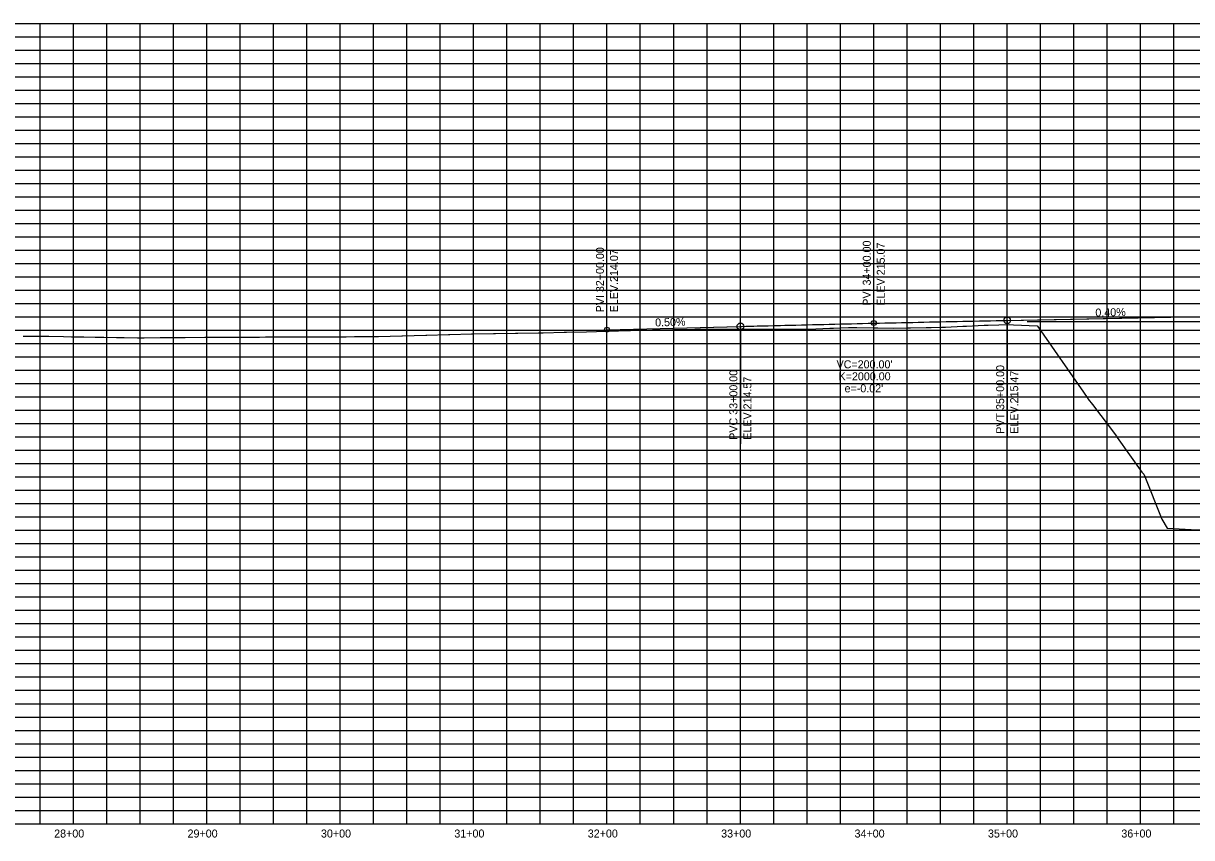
# Model space of a CAD drawing. Extents: x 1732967 to 1742744, y 374025 to 374739.
# Drawn here: x 1740676 to 1741552, y 374119 to 374730 of the extents above; entities that cross this region are included whole.
import ezdxf

# ---------------------------------------------------------------- set-up
doc = ezdxf.new("R2010")
doc.units = 0
for name, color, linetype in [('Level 8', 7, 'Continuous'), ('R_Axis_Annotation', 7, 'Continuous'), ('R_Exist Surface', 7, 'Continuous'), ('R_Grid', 7, 'Continuous'), ('R_Grid_Minor', 7, 'Continuous'), ('R_Horz Alg', 7, 'Continuous'), ('R_Vert Alg', 7, 'Continuous'), ('R_Vert Alg Annot', 7, 'Continuous')]:
    doc.layers.add(name, color=color, linetype=linetype)

msp = doc.modelspace()

# ---------------------------------------------------------------- linework, layer by layer
at = {"layer": 'Level 8'}
msp.add_line((1741428.91, 374506.11), (1741983.91, 374506.11), dxfattribs=at)
at = {"layer": 'R_Exist Surface'}
msp.add_lwpolyline([(1740676.24, 374495.2), (1740677.05, 374495.2), (1740677.87, 374495.19), (1740691.37, 374495.12), (1740694.78, 374495.1), (1740695.45, 374495.09), (1740706.51, 374494.86), (1740712.48, 374494.73), (1740712.84, 374494.72), (1740721.65, 374494.53), (1740730.12, 374494.34), (1740730.22, 374494.34), (1740734.41, 374494.29), (1740736.79, 374494.26), (1740746.31, 374494.14), (1740751.93, 374494.07), (1740761.89, 374493.94), (1740762.41, 374493.93), (1740767.07, 374493.97), (1740778.92, 374494.06), (1740779.59, 374494.07), (1740780.26, 374494.08), (1740782.21, 374494.1), (1740796.76, 374494.22), (1740797.35, 374494.23), (1740797.6, 374494.23), (1740812.49, 374494.26), (1740815.52, 374494.27), (1740827.62, 374494.29), (1740833.23, 374494.3), (1740834.28, 374494.32), (1740842.76, 374494.4), (1740851.74, 374494.48), (1740852.56, 374494.48), (1740853.37, 374494.48), (1740857.9, 374494.52), (1740870.85, 374494.64), (1740871.42, 374494.63), (1740873.04, 374494.63), (1740888.18, 374494.62), (1740888.8, 374494.62), (1740889.33, 374494.62), (1740903.32, 374494.6), (1740906.74, 374494.6), (1740907.14, 374494.6), (1740918.46, 374494.72), (1740924.63, 374494.79), (1740924.78, 374494.79), (1740933.6, 374494.88), (1740934.17, 374494.89), (1740942.36, 374494.96), (1740942.51, 374494.96), (1740960.24, 374495.4), (1740960.63, 374495.42), (1740978.12, 374495.86), (1740978.74, 374495.87), (1740995.2, 374496.35), (1740996.11, 374496.37), (1741012.27, 374496.84), (1741013.48, 374496.87), (1741028.86, 374497.05), (1741030.23, 374497.07), (1741045.39, 374497.25), (1741046.98, 374497.28), (1741062.63, 374497.62), (1741064.36, 374497.65), (1741066.1, 374497.68), (1741081.73, 374498.03), (1741083.51, 374498.08), (1741098.5, 374498.43), (1741113.53, 374498.78), (1741115.28, 374498.83), (1741130.01, 374499.24), (1741131.65, 374499.3), (1741146.46, 374499.71), (1741148.02, 374499.76), (1741163.15, 374500.03), (1741164.53, 374500.01), (1741179.86, 374500.29), (1741181.05, 374500.28), (1741182.06, 374500.3), (1741193.99, 374500.4), (1741195.28, 374500.44), (1741209.02, 374500.42), (1741221.06, 374500.42), (1741222.66, 374500.43), (1741234.83, 374500.44), (1741236.17, 374500.48), (1741247.91, 374500.42), (1741248.97, 374500.45), (1741260.84, 374500.39), (1741264.71, 374500.44), (1741265.34, 374500.46), (1741270.46, 374500.73), (1741280.85, 374501.18), (1741283.71, 374501.16), (1741294.89, 374501.66), (1741297.53, 374501.62), (1741301.32, 374501.54), (1741313.37, 374501.35), (1741316.86, 374501.37), (1741328.59, 374501.19), (1741338.49, 374501.27), (1741341.56, 374501.4), (1741353.1, 374501.61), (1741355.53, 374501.68), (1741356.85, 374501.73), (1741364.75, 374501.85), (1741367.72, 374501.96), (1741380.71, 374502.55), (1741383.49, 374502.65), (1741396.66, 374503.25), (1741399.56, 374503.37), (1741415.69, 374503.77), (1741418.61, 374503.53), (1741436.4, 374502.88), (1741437.34, 374501.71), (1741471.07, 374453.23), (1741474.45, 374448.32), (1741474.59, 374448.19), (1741474.74, 374448), (1741477.82, 374443.92), (1741495.83, 374420.05), (1741496.41, 374419.24), (1741514.96, 374393.26), (1741516.32, 374391.71), (1741516.41, 374391.65), (1741517.15, 374389.91), (1741529.42, 374359.27), (1741529.95, 374357.89), (1741533.72, 374351.3), (1741551.93, 374350.3), (1741558.51, 374349.94)], dxfattribs=at)
at = {"layer": 'R_Grid'}
for p, q in [((1739913.91, 374729.61), (1742713.91, 374729.61)), ((1740713.91, 374129.61), (1740713.91, 374729.61)), ((1740813.91, 374129.61), (1740813.91, 374729.61)), ((1740913.91, 374129.61), (1740913.91, 374729.61)), ((1741013.91, 374129.61), (1741013.91, 374729.61)), ((1741113.91, 374129.61), (1741113.91, 374729.61)), ((1741213.91, 374129.61), (1741213.91, 374729.61)), ((1741313.91, 374129.61), (1741313.91, 374729.61)), ((1741413.91, 374129.61), (1741413.91, 374729.61)), ((1741513.91, 374129.61), (1741513.91, 374729.61)), ((1739913.91, 374679.61), (1742713.91, 374679.61)), ((1739913.91, 374629.61), (1742713.91, 374629.61)), ((1739913.91, 374579.61), (1742713.91, 374579.61)), ((1739913.91, 374529.61), (1742713.91, 374529.61)), ((1739913.91, 374479.61), (1742713.91, 374479.61)), ((1739913.91, 374429.61), (1742713.91, 374429.61)), ((1739913.91, 374379.61), (1742713.91, 374379.61)), ((1739913.91, 374329.61), (1742713.91, 374329.61)), ((1739913.91, 374279.61), (1742713.91, 374279.61)), ((1739913.91, 374229.61), (1742713.91, 374229.61)), ((1739913.91, 374179.61), (1742713.91, 374179.61)), ((1739913.91, 374129.61), (1742713.91, 374129.61))]:
    msp.add_line(p, q, dxfattribs=at)
at = {"layer": 'R_Grid_Minor'}
for p, q in [((1740688.91, 374129.61), (1740688.91, 374729.61)), ((1740738.91, 374129.61), (1740738.91, 374729.61)), ((1740763.91, 374129.61), (1740763.91, 374729.61)), ((1740788.91, 374129.61), (1740788.91, 374729.61)), ((1740838.91, 374129.61), (1740838.91, 374729.61)), ((1740863.91, 374129.61), (1740863.91, 374729.61)), ((1740888.91, 374129.61), (1740888.91, 374729.61)), ((1740938.91, 374129.61), (1740938.91, 374729.61)), ((1740963.91, 374129.61), (1740963.91, 374729.61)), ((1740988.91, 374129.61), (1740988.91, 374729.61)), ((1741038.91, 374129.61), (1741038.91, 374729.61)), ((1741063.91, 374129.61), (1741063.91, 374729.61)), ((1741088.91, 374129.61), (1741088.91, 374729.61)), ((1741138.91, 374129.61), (1741138.91, 374729.61)), ((1741163.91, 374129.61), (1741163.91, 374729.61)), ((1741188.91, 374129.61), (1741188.91, 374729.61)), ((1741238.91, 374129.61), (1741238.91, 374729.61)), ((1741263.91, 374129.61), (1741263.91, 374729.61)), ((1741288.91, 374129.61), (1741288.91, 374729.61)), ((1741338.91, 374129.61), (1741338.91, 374729.61)), ((1741363.91, 374129.61), (1741363.91, 374729.61)), ((1741388.91, 374129.61), (1741388.91, 374729.61)), ((1741438.91, 374129.61), (1741438.91, 374729.61)), ((1741463.91, 374129.61), (1741463.91, 374729.61)), ((1741488.91, 374129.61), (1741488.91, 374729.61)), ((1741538.91, 374129.61), (1741538.91, 374729.61)), ((1739913.91, 374719.61), (1742713.91, 374719.61)), ((1739913.91, 374709.61), (1742713.91, 374709.61)), ((1739913.91, 374699.61), (1742713.91, 374699.61)), ((1739913.91, 374689.61), (1742713.91, 374689.61)), ((1739913.91, 374669.61), (1742713.91, 374669.61)), ((1739913.91, 374659.61), (1742713.91, 374659.61)), ((1739913.91, 374649.61), (1742713.91, 374649.61)), ((1739913.91, 374639.61), (1742713.91, 374639.61)), ((1739913.91, 374619.61), (1742713.91, 374619.61)), ((1739913.91, 374609.61), (1742713.91, 374609.61)), ((1739913.91, 374599.61), (1742713.91, 374599.61)), ((1739913.91, 374589.61), (1742713.91, 374589.61)), ((1739913.91, 374569.61), (1742713.91, 374569.61)), ((1739913.91, 374559.61), (1742713.91, 374559.61)), ((1739913.91, 374549.61), (1742713.91, 374549.61)), ((1739913.91, 374539.61), (1742713.91, 374539.61)), ((1739913.91, 374519.61), (1742713.91, 374519.61)), ((1739913.91, 374509.61), (1742713.91, 374509.61)), ((1739913.91, 374499.61), (1742713.91, 374499.61)), ((1739913.91, 374489.61), (1742713.91, 374489.61)), ((1739913.91, 374469.61), (1742713.91, 374469.61)), ((1739913.91, 374459.61), (1742713.91, 374459.61)), ((1739913.91, 374449.61), (1742713.91, 374449.61)), ((1739913.91, 374439.61), (1742713.91, 374439.61)), ((1739913.91, 374419.61), (1742713.91, 374419.61)), ((1739913.91, 374409.61), (1742713.91, 374409.61)), ((1739913.91, 374399.61), (1742713.91, 374399.61)), ((1739913.91, 374389.61), (1742713.91, 374389.61)), ((1739913.91, 374369.61), (1742713.91, 374369.61)), ((1739913.91, 374359.61), (1742713.91, 374359.61)), ((1739913.91, 374349.61), (1742713.91, 374349.61)), ((1739913.91, 374339.61), (1742713.91, 374339.61)), ((1739913.91, 374319.61), (1742713.91, 374319.61)), ((1739913.91, 374309.61), (1742713.91, 374309.61)), ((1739913.91, 374299.61), (1742713.91, 374299.61)), ((1739913.91, 374289.61), (1742713.91, 374289.61)), ((1739913.91, 374269.61), (1742713.91, 374269.61)), ((1739913.91, 374259.61), (1742713.91, 374259.61)), ((1739913.91, 374249.61), (1742713.91, 374249.61)), ((1739913.91, 374239.61), (1742713.91, 374239.61)), ((1739913.91, 374219.61), (1742713.91, 374219.61)), ((1739913.91, 374209.61), (1742713.91, 374209.61)), ((1739913.91, 374199.61), (1742713.91, 374199.61)), ((1739913.91, 374189.61), (1742713.91, 374189.61)), ((1739913.91, 374169.61), (1742713.91, 374169.61)), ((1739913.91, 374159.61), (1742713.91, 374159.61)), ((1739913.91, 374149.61), (1742713.91, 374149.61)), ((1739913.91, 374139.61), (1742713.91, 374139.61))]:
    msp.add_line(p, q, dxfattribs=at)
at = {"layer": 'R_Horz Alg'}
for p, q in [((1741313.91, 374504.96), (1741773.91, 374514.16)), ((1741313.91, 374504.96), (1741773.91, 374514.16)), ((1741413.91, 374506.96), (1741773.91, 374514.16)), ((1741413.91, 374506.96), (1741573.91, 374510.16)), ((1741413.91, 374506.96), (1741573.91, 374510.16)), ((1741413.91, 374506.96), (1741548.91, 374509.66)), ((1741413.91, 374506.96), (1741548.91, 374509.66)), ((1741413.91, 374506.96), (1741523.91, 374509.16)), ((1741113.91, 374499.96), (1741313.91, 374504.96)), ((1741113.91, 374499.96), (1741313.91, 374504.96)), ((1741113.91, 374499.96), (1741213.91, 374502.46)), ((1741113.91, 374499.96), (1741213.91, 374502.46)), ((1741113.91, 374499.96), (1741213.91, 374502.46)), ((1741113.91, 374499.96), (1741213.91, 374502.46)), ((1741113.91, 374499.96), (1741213.91, 374502.46)), ((1741113.91, 374499.96), (1741213.91, 374502.46))]:
    msp.add_line(p, q, dxfattribs=at)
msp.add_lwpolyline([(1741213.91, 374502.46), (1741218.08, 374502.57), (1741222.24, 374502.67), (1741226.41, 374502.77), (1741230.58, 374502.88), (1741234.74, 374502.98), (1741238.91, 374503.08), (1741243.08, 374503.18), (1741247.24, 374503.28), (1741251.41, 374503.38), (1741255.58, 374503.48), (1741259.74, 374503.58), (1741263.91, 374503.68), (1741268.08, 374503.78), (1741272.24, 374503.88), (1741276.41, 374503.98), (1741280.58, 374504.07), (1741284.74, 374504.17), (1741288.91, 374504.27), (1741293.08, 374504.36), (1741297.24, 374504.46), (1741301.41, 374504.56), (1741305.58, 374504.65), (1741309.74, 374504.74), (1741318.08, 374504.93), (1741322.24, 374505.03), (1741326.41, 374505.12), (1741330.58, 374505.21), (1741334.74, 374505.3), (1741338.91, 374505.39), (1741343.08, 374505.48), (1741347.24, 374505.57), (1741351.41, 374505.66), (1741355.58, 374505.75), (1741359.74, 374505.84), (1741363.91, 374505.93), (1741368.08, 374506.02), (1741372.24, 374506.11), (1741376.41, 374506.2), (1741380.58, 374506.28), (1741384.74, 374506.37), (1741388.91, 374506.46), (1741393.08, 374506.54), (1741397.24, 374506.63), (1741401.41, 374506.71), (1741405.58, 374506.8), (1741409.74, 374506.88), (1741413.91, 374506.96)], dxfattribs=at)
msp.add_lwpolyline([(1741213.91, 374502.46), (1741218.08, 374502.57), (1741222.24, 374502.67), (1741226.41, 374502.77), (1741230.58, 374502.88), (1741234.74, 374502.98), (1741238.91, 374503.08), (1741243.08, 374503.18), (1741247.24, 374503.28), (1741251.41, 374503.38), (1741255.58, 374503.48), (1741259.74, 374503.58), (1741263.91, 374503.68), (1741268.08, 374503.78), (1741272.24, 374503.88), (1741276.41, 374503.98), (1741280.58, 374504.07), (1741284.74, 374504.17), (1741288.91, 374504.27), (1741293.08, 374504.36), (1741297.24, 374504.46), (1741301.41, 374504.56), (1741305.58, 374504.65), (1741309.74, 374504.74), (1741318.08, 374504.93), (1741322.24, 374505.03), (1741326.41, 374505.12), (1741330.58, 374505.21), (1741334.74, 374505.3), (1741338.91, 374505.39), (1741343.08, 374505.48), (1741347.24, 374505.57), (1741351.41, 374505.66), (1741355.58, 374505.75), (1741359.74, 374505.84), (1741363.91, 374505.93), (1741368.08, 374506.02), (1741372.24, 374506.11), (1741376.41, 374506.2), (1741380.58, 374506.28), (1741384.74, 374506.37), (1741388.91, 374506.46), (1741393.08, 374506.54), (1741397.24, 374506.63), (1741401.41, 374506.71), (1741405.58, 374506.8), (1741409.74, 374506.88), (1741413.91, 374506.96)], dxfattribs=at)
msp.add_lwpolyline([(1741213.91, 374502.46), (1741218.08, 374502.57), (1741222.24, 374502.67), (1741226.41, 374502.77), (1741230.58, 374502.88), (1741234.74, 374502.98), (1741238.91, 374503.08), (1741243.08, 374503.18), (1741247.24, 374503.28), (1741251.41, 374503.38), (1741255.58, 374503.48), (1741259.74, 374503.58), (1741263.91, 374503.68), (1741268.08, 374503.78), (1741272.24, 374503.88), (1741276.41, 374503.98), (1741280.58, 374504.07), (1741284.74, 374504.17), (1741288.91, 374504.27), (1741293.08, 374504.36), (1741297.24, 374504.46), (1741301.41, 374504.56), (1741305.58, 374504.65), (1741309.74, 374504.74), (1741318.08, 374504.93), (1741322.24, 374505.03), (1741326.41, 374505.12), (1741330.58, 374505.21), (1741334.74, 374505.3), (1741338.91, 374505.39), (1741343.08, 374505.48), (1741347.24, 374505.57), (1741351.41, 374505.66), (1741355.58, 374505.75), (1741359.74, 374505.84), (1741363.91, 374505.93), (1741368.08, 374506.02), (1741372.24, 374506.11), (1741376.41, 374506.2), (1741380.58, 374506.28), (1741384.74, 374506.37), (1741388.91, 374506.46), (1741393.08, 374506.54), (1741397.24, 374506.63), (1741401.41, 374506.71), (1741405.58, 374506.8), (1741409.74, 374506.88), (1741413.91, 374506.96)], dxfattribs=at)
msp.add_lwpolyline([(1741213.91, 374502.46), (1741218.08, 374502.57), (1741222.24, 374502.67), (1741226.41, 374502.77), (1741230.58, 374502.88), (1741234.74, 374502.98), (1741238.91, 374503.08), (1741243.08, 374503.18), (1741247.24, 374503.28), (1741251.41, 374503.38), (1741255.58, 374503.48), (1741259.74, 374503.58), (1741263.91, 374503.68), (1741268.08, 374503.78), (1741272.24, 374503.88), (1741276.41, 374503.98), (1741280.58, 374504.07), (1741284.74, 374504.17), (1741288.91, 374504.27), (1741293.08, 374504.36), (1741297.24, 374504.46), (1741301.41, 374504.56), (1741305.58, 374504.65), (1741309.74, 374504.74), (1741318.08, 374504.93), (1741322.24, 374505.03), (1741326.41, 374505.12), (1741330.58, 374505.21), (1741334.74, 374505.3), (1741338.91, 374505.39), (1741343.08, 374505.48), (1741347.24, 374505.57), (1741351.41, 374505.66), (1741355.58, 374505.75), (1741359.74, 374505.84), (1741363.91, 374505.93), (1741368.08, 374506.02), (1741372.24, 374506.11), (1741376.41, 374506.2), (1741380.58, 374506.28), (1741384.74, 374506.37), (1741388.91, 374506.46), (1741393.08, 374506.54), (1741397.24, 374506.63), (1741401.41, 374506.71), (1741405.58, 374506.8), (1741409.74, 374506.88), (1741413.91, 374506.96)], dxfattribs=at)
msp.add_lwpolyline([(1741213.91, 374502.46), (1741218.08, 374502.57), (1741222.24, 374502.67), (1741226.41, 374502.77), (1741230.58, 374502.88), (1741234.74, 374502.98), (1741238.91, 374503.08), (1741243.08, 374503.18), (1741247.24, 374503.28), (1741251.41, 374503.38), (1741255.58, 374503.48), (1741259.74, 374503.58), (1741263.91, 374503.68), (1741268.08, 374503.78), (1741272.24, 374503.88), (1741276.41, 374503.98), (1741280.58, 374504.07), (1741284.74, 374504.17), (1741288.91, 374504.27), (1741293.08, 374504.36), (1741297.24, 374504.46), (1741301.41, 374504.56), (1741305.58, 374504.65), (1741309.74, 374504.74), (1741318.08, 374504.93), (1741322.24, 374505.03), (1741326.41, 374505.12), (1741330.58, 374505.21), (1741334.74, 374505.3), (1741338.91, 374505.39), (1741343.08, 374505.48), (1741347.24, 374505.57), (1741351.41, 374505.66), (1741355.58, 374505.75), (1741359.74, 374505.84), (1741363.91, 374505.93), (1741368.08, 374506.02), (1741372.24, 374506.11), (1741376.41, 374506.2), (1741380.58, 374506.28), (1741384.74, 374506.37), (1741388.91, 374506.46), (1741393.08, 374506.54), (1741397.24, 374506.63), (1741401.41, 374506.71), (1741405.58, 374506.8), (1741409.74, 374506.88), (1741413.91, 374506.96)], dxfattribs=at)
msp.add_lwpolyline([(1741213.91, 374502.46), (1741218.08, 374502.57), (1741222.24, 374502.67), (1741226.41, 374502.77), (1741230.58, 374502.88), (1741234.74, 374502.98), (1741238.91, 374503.08), (1741243.08, 374503.18), (1741247.24, 374503.28), (1741251.41, 374503.38), (1741255.58, 374503.48), (1741259.74, 374503.58), (1741263.91, 374503.68), (1741268.08, 374503.78), (1741272.24, 374503.88), (1741276.41, 374503.98), (1741280.58, 374504.07), (1741284.74, 374504.17), (1741288.91, 374504.27), (1741293.08, 374504.36), (1741297.24, 374504.46), (1741301.41, 374504.56), (1741305.58, 374504.65), (1741309.74, 374504.74), (1741318.08, 374504.93), (1741322.24, 374505.03), (1741326.41, 374505.12), (1741330.58, 374505.21), (1741334.74, 374505.3), (1741338.91, 374505.39), (1741343.08, 374505.48), (1741347.24, 374505.57), (1741351.41, 374505.66), (1741355.58, 374505.75), (1741359.74, 374505.84), (1741363.91, 374505.93), (1741368.08, 374506.02), (1741372.24, 374506.11), (1741376.41, 374506.2), (1741380.58, 374506.28), (1741384.74, 374506.37), (1741388.91, 374506.46), (1741393.08, 374506.54), (1741397.24, 374506.63), (1741401.41, 374506.71), (1741405.58, 374506.8), (1741409.74, 374506.88), (1741413.91, 374506.96)], dxfattribs=at)
at = {"layer": 'R_Vert Alg'}
for p, q in [((1741413.91, 374506.96), (1741573.91, 374510.16)), ((1741113.91, 374499.96), (1741213.91, 374502.46))]:
    msp.add_line(p, q, dxfattribs=at)
msp.add_lwpolyline([(1741213.91, 374502.46), (1741218.08, 374502.57), (1741222.24, 374502.67), (1741226.41, 374502.77), (1741230.58, 374502.88), (1741234.74, 374502.98), (1741238.91, 374503.08), (1741243.08, 374503.18), (1741247.24, 374503.28), (1741251.41, 374503.38), (1741255.58, 374503.48), (1741259.74, 374503.58), (1741263.91, 374503.68), (1741268.08, 374503.78), (1741272.24, 374503.88), (1741276.41, 374503.98), (1741280.58, 374504.07), (1741284.74, 374504.17), (1741288.91, 374504.27), (1741293.08, 374504.36), (1741297.24, 374504.46), (1741301.41, 374504.56), (1741305.58, 374504.65), (1741309.74, 374504.74), (1741318.08, 374504.93), (1741322.24, 374505.03), (1741326.41, 374505.12), (1741330.58, 374505.21), (1741334.74, 374505.3), (1741338.91, 374505.39), (1741343.08, 374505.48), (1741347.24, 374505.57), (1741351.41, 374505.66), (1741355.58, 374505.75), (1741359.74, 374505.84), (1741363.91, 374505.93), (1741368.08, 374506.02), (1741372.24, 374506.11), (1741376.41, 374506.2), (1741380.58, 374506.28), (1741384.74, 374506.37), (1741388.91, 374506.46), (1741393.08, 374506.54), (1741397.24, 374506.63), (1741401.41, 374506.71), (1741405.58, 374506.8), (1741409.74, 374506.88), (1741413.91, 374506.96)], dxfattribs=at)
at = {"layer": 'R_Vert Alg Annot'}
for p, q in [((1741113.91, 374509.96), (1741113.91, 374587.96)), ((1741313.91, 374514.96), (1741313.91, 374592.96)), ((1741113.91, 374499.96), (1741113.91, 374509.96)), ((1741313.91, 374504.96), (1741313.91, 374514.96)), ((1741213.91, 374502.46), (1741213.91, 374492.46)), ((1741263.91, 374503.71), (1741313.91, 374504.96)), ((1741313.91, 374504.96), (1741363.91, 374505.96)), ((1741413.91, 374506.96), (1741413.91, 374496.96)), ((1741213.91, 374492.46), (1741213.91, 374414.46)), ((1741413.91, 374496.96), (1741413.91, 374418.96))]:
    msp.add_line(p, q, dxfattribs=at)
for centre, radius in [((1741413.91, 374506.96), 2.5), ((1741113.91, 374499.96), 1.85), ((1741213.91, 374502.46), 2.5), ((1741313.91, 374504.96), 1.85)]:
    msp.add_circle(centre, radius, dxfattribs=at)

# ---------------------------------------------------------------- texts
at = {"layer": 'R_Axis_Annotation'}
for s, p in [('28+00', (1740699.5, 374119.26)), ('29+00', (1740799.5, 374119.26)), ('30+00', (1740899.5, 374119.26)), ('31+00', (1740999.5, 374119.26)), ('32+00', (1741099.5, 374119.26)), ('33+00', (1741199.5, 374119.26)), ('34+00', (1741299.5, 374119.26)), ('35+00', (1741399.5, 374119.26)), ('36+00', (1741499.5, 374119.26))]:
    msp.add_text(s, height=6, dxfattribs=at).set_placement(p)
at = {"layer": 'R_Vert Alg Annot'}
for s, rotation, p in [('PVI 32+00.00', 90, (1741111.66, 374512.96)), ('PVI 34+00.00', 90, (1741311.66, 374517.96)), ('ELEV.215.07', 90, (1741322.16, 374517.96)), ('ELEV.214.07', 90, (1741122.16, 374512.96)), ('0.50%', 1.4321, (1741150.08, 374502.37)), ('0.40%', 1.14576, (1741480.08, 374509.79)), ('PVC 33+00.00', 90, (1741211.66, 374417.46)), ('PVT 35+00.00', 90, (1741411.66, 374421.96)), ('ELEV.215.47', 90, (1741422.16, 374421.96)), ('ELEV.214.57', 90, (1741222.16, 374417.46))]:
    msp.add_text(s, height=6, rotation=rotation, dxfattribs=at).set_placement(p)
for s, p in [("VC=200.00'", (1741286.01, 374471.01)), ('K=2000.00', (1741287.5, 374462.01)), ("e=-0.02'", (1741292.01, 374453.01))]:
    msp.add_text(s, height=6, dxfattribs=at).set_placement(p)

doc.saveas('drawing.dxf')
